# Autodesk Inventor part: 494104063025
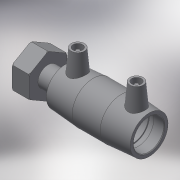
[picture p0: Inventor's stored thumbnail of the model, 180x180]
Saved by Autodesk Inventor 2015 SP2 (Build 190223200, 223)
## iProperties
Created: 2017-06
Part Number: 494104063025
Material: Generic
Description: PLASSON FEMALE FREE NUT TRANSITION COUPLER 63-2½''
Document SubType Name: Modeling
Designer: KIM
Mass: 55.0731 g
Surface Area: 148.067 cm^2
Volume: 55.0731 cm^3
Density: 1 g/cm^3
Appearance: Default
Author: KIM
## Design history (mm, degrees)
derived "494104.ipt"
feature "Solid1::494104.ipt"
tag "TaggingFeature1"
body "Solid1"
other parameters: "d0" = 117, "d1" = 63, "d2" = 82, "d3" = 57, "d4" = 39, "d5" = 73.8, "d6" = 59.85, "d7" = 63, "d8" = 168 deg, "d10" = 22.8, "d11" = 7.6, "d29" = 57, "d30" = 14, "d31" = 40.95, "d34" = 5 deg, "d41" = 4, "d42" = 14, "d43" = 0, "d48" = 3, "d49" = 0, "d55" = 49, "d57" = 48, "d80" = 1.26, "d83" = 24.5, "d84" = 16.17, "d85" = 1.617, "d86" = 57.7808, "d87" = 72.226, "d88" = 108.339, "d89" = 82, "d90" = 2.16678, "d94" = 0, "d95" = 1.617, "d96" = 50.5582, "d_" = 63, "L_" = 166, "L_1" = 57, "D_1" = 82, "A_" = 57, "d_2" = 12, "L_2" = 49, "D_" = 48, "G_" = 72.226
